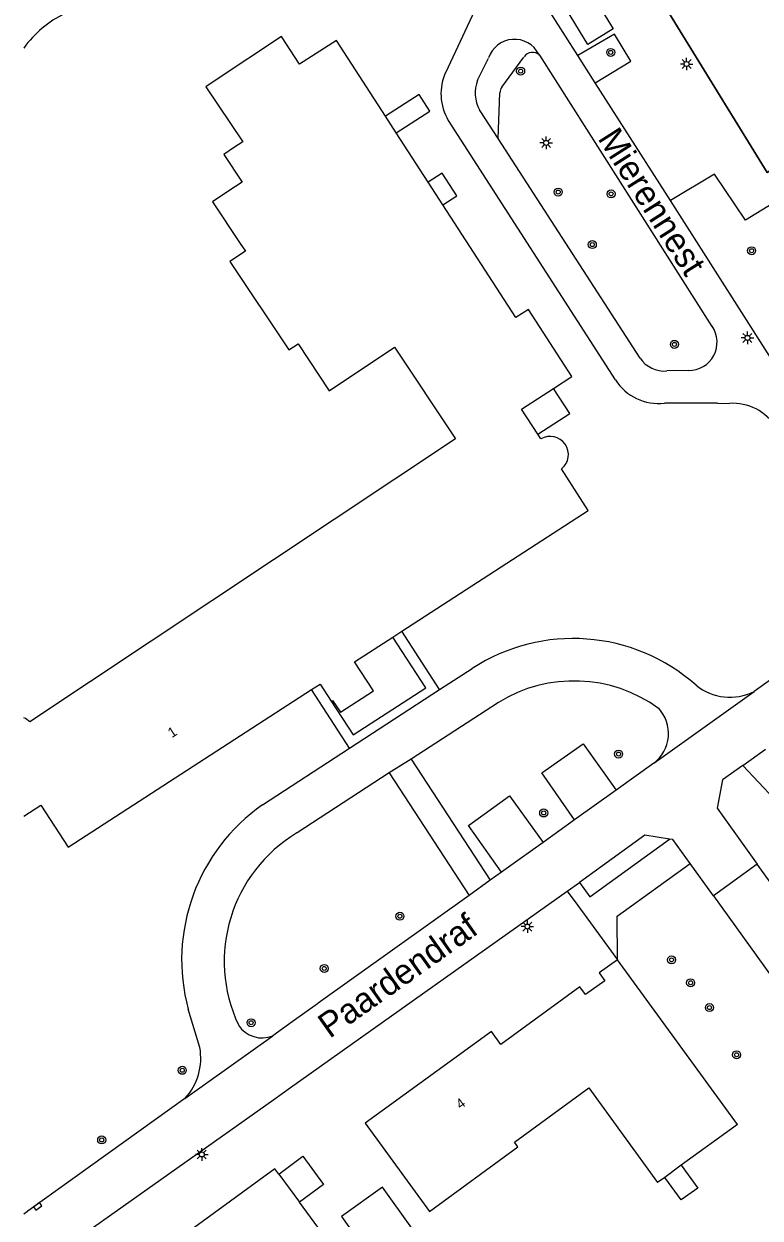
# Model space of a CAD drawing. Extents: x 141000 to 143000, y 400580 to 403500.
# Drawn here: x 141000 to 141073.5, y 403024.1 to 403143.4 of the extents above; entities that cross this region are included whole.
import ezdxf

# ---------------------------------------------------------------- set-up
doc = ezdxf.new("R2010")
doc.units = 0
for name, color, linetype in [('gg-afsc-erfafscheiding', 7, 'Continuous'), ('gg-afsc-hekwerk', 7, 'Continuous'), ('gg-anno-huisnummerreeks BGT', 7, 'Continuous'), ('gg-anno-openbare ruimte label', 7, 'Continuous'), ('gg-bbg-bijgebouw', 7, 'Continuous'), ('gg-bbg-gedigitaliseerde bijgebouw', 7, 'Continuous'), ('gg-bbg-hoofdgebouw', 7, 'Continuous'), ('gg-bbg-luifel en loopbrug', 7, 'Continuous'), ('gg-bbg-tussenscheiding', 7, 'Continuous'), ('gg-knt-verharding', 7, 'Continuous'), ('gg-knt-verharding nz', 7, 'Continuous'), ('gt-grn-groengrens', 7, 'Continuous'), ('gt-grn-vlakafsluiter', 7, 'Continuous'), ('gt-symb-boom', 7, 'Continuous'), ('gt-symb-kolk', 7, 'Continuous'), ('gt-symb-lichtmast', 7, 'Continuous')]:
    doc.layers.add(name, color=color, linetype=linetype)

# ---------------------------------------------------------------- blocks, each defined once
blk = doc.blocks.new('gt0-LMAST')
at = {"layer": 'gt-symb-lichtmast'}
for p, q in [((-0.18, 0.17), (-0.45, 0.44)), ((-0.01, 0.25), (-0.01, 0.62)), ((0.17, 0.17), (0.44, 0.44)), ((-0.26, 0), (-0.63, 0)), ((-0.18, -0.18), (-0.45, -0.45)), ((-0.01, -0.25), (-0.01, -0.63)), ((0.44, -0.45), (0.17, -0.18)), ((0.24, 0), (0.62, 0))]:
    blk.add_line(p, q, dxfattribs=at)
blk.add_circle((-0.01, 0), 0.25, dxfattribs=at)
blk = doc.blocks.new('gt0-BOOM')
at = {"layer": 'gt-symb-boom'}
for radius in [0.4, 0.2]:
    blk.add_circle((0, 0), radius, dxfattribs=at)
blk = doc.blocks.new('gt0-KOLK')
at = {"layer": 'gt-symb-kolk'}
blk.add_lwpolyline([(0, 0), (0.37, 0), (0.37, 0.4), (-0.38, 0.4), (-0.38, 0), (0, 0)], dxfattribs=at)

msp = doc.modelspace()

# ---------------------------------------------------------------- linework, layer by layer
at = {"layer": 'gg-afsc-erfafscheiding'}
msp.add_line((141057.08, 403137.55), (141055.34, 403140.28), dxfattribs=at)
at = {"layer": 'gg-afsc-hekwerk'}
msp.add_lwpolyline([(141060.06, 403151.69), (141094.93, 403173.23), (141109.35, 403150.25), (141074.26, 403128.6), (141060.06, 403151.69)], dxfattribs=at)
at = {"layer": 'gg-bbg-bijgebouw'}
msp.add_lwpolyline([(141034.65, 403020.12), (141038.76, 403023.06), (141035.82, 403027.17), (141031.71, 403024.23), (141034.65, 403020.12)], dxfattribs=at)
at = {"layer": 'gg-bbg-gedigitaliseerde bijgebouw'}
for points in [[(141056.72, 403146.43), (141058.87, 403142.95), (141056.33, 403141.39), (141054.19, 403144.87)], [(141037.2, 403132.54), (141040.55, 403134.71), (141039.47, 403136.39), (141036.11, 403134.22)]]:
    msp.add_lwpolyline(points, dxfattribs=at)
at = {"layer": 'gg-bbg-hoofdgebouw'}
for p, q in [((141040.38, 403127.61), (141037.2, 403132.54)), ((141041.85, 403125.35), (141040.38, 403127.61)), ((141051.65, 403101.96), (141051.35, 403102.43)), ((141036.85, 403082.16), (141037.74, 403082.74)), ((141071.27, 403033.43), (141059.28, 403049.89)), ((141071.27, 403033.43), (141065.67, 403029.36)), ((141025.45, 403028.48), (141027.52, 403025.66)), ((141065.67, 403029.36), (141064.01, 403028.15)), ((141064.01, 403028.15), (141063.3, 403027.64))]:
    msp.add_line(p, q, dxfattribs=at)
for points in [[(141036.11, 403134.22), (141031.21, 403141.78), (141027.53, 403139.4), (141025.73, 403142.18), (141019.12, 403137.78), (141018.19, 403137.16), (141021.86, 403131.65), (141020.94, 403131.04), (141019.97, 403130.39), (141021.8, 403127.63), (141020.48, 403126.75), (141018.83, 403125.65), (141021.59, 403121.49), (141022.13, 403120.74), (141020.57, 403119.68), (141026.45, 403110.85), (141027.39, 403111.47), (141030.5, 403106.78), (141037.03, 403111.12), (141043.12, 403101.97), (141000.6, 403073.67), (141000.15, 403074.03), (141000, 403074.07)], [(141052.9, 403107.01), (141054.74, 403108.2), (141050.41, 403114.89), (141049.14, 403114.09), (141041.85, 403125.35)], [(141051.35, 403102.43), (141049.71, 403104.94), (141052.9, 403107.01)], [(141037.74, 403082.74), (141056.36, 403094.8), (141053.71, 403098.98)], [(141030.7, 403075.74), (141030.84, 403075.83), (141031.61, 403074.64), (141034.91, 403076.78), (141033.03, 403079.69), (141036.85, 403082.16)], [(141028.72, 403076.9), (141029.59, 403077.46), (141030.7, 403075.74)], [(141000, 403064.24), (141001.7, 403065.34), (141004.43, 403061.17), (141028.72, 403076.9)], [(141059.28, 403049.89), (141057.47, 403048.58), (141058.03, 403047.81), (141056.1, 403046.42), (141055.54, 403047.19), (141047.64, 403041.43), (141046.7, 403042.73), (141034.08, 403033.56), (141040.5, 403024.75), (141049.35, 403031.19), (141049, 403031.68), (141056.43, 403037.09), (141063.3, 403027.64)], [(141025.45, 403028.48), (141025.08, 403028.99), (141011.43, 403019.05)], [(141022.4, 403014.93), (141022.57, 403015.05), (141030.83, 403021.16), (141027.52, 403025.66)]]:
    msp.add_lwpolyline(points, dxfattribs=at)
msp.add_arc((141052.58, 403100.4), 1.81, 308.4698, 120.8064, dxfattribs=at)
at = {"layer": 'gg-bbg-luifel en loopbrug'}
for points in [[(141041.85, 403125.35), (141043.24, 403126.24), (141041.77, 403128.51), (141040.38, 403127.61)], [(141051.35, 403102.43), (141054.53, 403104.5), (141052.9, 403107.01)], [(141030.7, 403075.74), (141032.88, 403072.38), (141040.14, 403077.09), (141036.85, 403082.16)], [(141025.45, 403028.48), (141027.87, 403030.26), (141029.94, 403027.44), (141027.52, 403025.66)], [(141065.67, 403029.36), (141067.33, 403027.07), (141065.65, 403025.89), (141064.01, 403028.15)]]:
    msp.add_lwpolyline(points, dxfattribs=at)
at = {"layer": 'gg-bbg-tussenscheiding'}
msp.add_line((141037.2, 403132.54), (141036.11, 403134.22), dxfattribs=at)
at = {"layer": 'gg-knt-verharding'}
for p, q in [((141055.34, 403140.28), (141050.74, 403147.51)), ((141045.23, 403145.26), (141042.14, 403138.63)), ((141051.51, 403140.3), (141051.44, 403140.41)), ((141045.32, 403137.8), (141046.41, 403140.03)), ((141051.51, 403140.3), (141068.73, 403113.21)), ((141064.58, 403125.78), (141057.08, 403137.55)), ((141059.09, 403107.86), (141042.4, 403133.79)), ((141061.56, 403110.03), (141047.36, 403131.97)), ((141077.33, 403105.75), (141064.58, 403125.78)), ((141066.38, 403108.8), (141064.22, 403108.75)), ((141069.28, 403105.52), (141063.99, 403105.53)), ((141069.28, 403105.52), (141070.47, 403105.51)), ((141082.19, 403083.34), (141072.93, 403076.71)), ((141041.53, 403076.9), (141037.74, 403082.74)), ((141041.53, 403076.9), (141044.77, 403079)), ((141032.52, 403071.04), (141028.72, 403076.9)), ((141047.4, 403075.62), (141038.68, 403069.96)), ((141023.84, 403065.38), (141032.52, 403071.04)), ((141038.68, 403069.96), (141046.56, 403057.84)), ((141071.83, 403069.33), (141074.09, 403070.94)), ((141062.93, 403069.56), (141059.15, 403066.85)), ((141071.83, 403069.33), (141074.93, 403065.98)), ((141036.49, 403068.58), (141027.28, 403062.58)), ((141036.49, 403068.58), (141044.47, 403056.34)), ((141059.15, 403066.85), (141055.01, 403063.89)), ((141055.01, 403063.89), (141051.86, 403061.63)), ((141068.88, 403056.29), (141066.55, 403059.51)), ((141073.24, 403059.44), (141068.88, 403056.29)), ((141077.74, 403053.2), (141073.24, 403059.44)), ((141047.71, 403058.66), (141046.56, 403057.84)), ((141046.56, 403057.84), (141044.47, 403056.34)), ((141054.27, 403056.76), (141055.49, 403057.63)), ((141054.27, 403056.76), (141055.32, 403055.32)), ((141068.88, 403056.29), (141096.13, 403018.32)), ((141017.57, 403041.14), (141016.41, 403044.96)), ((141000, 403024.52), (141000.36, 403024.78))]:
    msp.add_line(p, q, dxfattribs=at)
for points in [[(141054.55, 403150.07), (141057.4, 403145.7), (141059.93, 403147.32), (141056.4, 403152.91), (141094.62, 403176.46), (141102.17, 403164.21), (141102.7, 403164.56), (141105.03, 403160.96), (141104.42, 403160.54), (141111.86, 403148.25), (141072.07, 403123.82), (141069, 403128.42), (141064.58, 403125.78)], [(141109.35, 403150.25), (141094.93, 403173.23), (141060.06, 403151.69), (141074.26, 403128.6), (141109.35, 403150.25)], [(141057.08, 403137.55), (141060.64, 403139.71), (141058.98, 403142.42), (141055.34, 403140.28)], [(141047.36, 403131.97), (141045.56, 403134.75), (141045.5, 403134.84)], [(141055.01, 403063.89), (141051.74, 403068.57), (141055.87, 403071.47), (141059.15, 403066.85)], [(141071.83, 403069.33), (141069.79, 403067.87), (141069.26, 403065.05), (141073.24, 403059.44)], [(141047.71, 403058.66), (141044.4, 403063.33), (141048.5, 403066.27), (141051.86, 403061.63)], [(141051.86, 403061.63), (141050.59, 403060.72), (141049.58, 403060), (141047.71, 403058.66)], [(141064.48, 403061.96), (141062.01, 403062.34), (141055.49, 403057.63)], [(141055.49, 403057.63), (141056.53, 403056.2), (141064.48, 403061.96)], [(141066.55, 403059.51), (141064.81, 403061.91), (141064.48, 403061.96)], [(141059.28, 403049.89), (141059.25, 403054.25), (141066.55, 403059.51)], [(141000.61, 403018.66), (141001.04, 403018.97), (141024.96, 403035.95), (141026.63, 403037.14), (141054.27, 403056.76)], [(141044.47, 403056.34), (141029.38, 403045.55), (141029.33, 403045.51), (141026.81, 403043.7), (141024.87, 403042.31)], [(141016.09, 403036.04), (141000.51, 403024.88), (141000.36, 403024.78)]]:
    msp.add_lwpolyline(points, dxfattribs=at)
for centre, radius, start, end in [((141008.67, 403134.89), 10.62, 115.5854, 144.7235), ((141049, 403139.17), 2.73, 27.0386, 161.5341), ((141046.86, 403136.46), 5.2, 155.2991, 210.8545), ((141048.67, 403136.52), 3.59, 159.0325, 207.8526), ((141066.43, 403111.61), 2.81, 269.0996, 34.8243), ((141063.97, 403111.64), 2.9, 213.7414, 274.8996), ((141063.39, 403110.6), 5.1, 212.4457, 276.7383), ((141070.78, 403100.35), 5.17, 32.3901, 93.3858), ((141054.87, 403063.55), 18.46, 48.3559, 123.1711), ((141054.96, 403063.41), 14.36, 53.9893, 121.7899), ((141070.52, 403081.48), 5.34, 230.7467, 296.8574), ((141060.66, 403072.51), 3.73, 307.5813, 42.5189), ((141034.62, 403049.9), 18.86, 124.8483, 195.1815), ((141034.97, 403049.75), 14.96, 120.9432, 205.1913), ((141023.78, 403044.88), 2.79, 212.6282, 292.9319), ((141011.76, 403040.06), 5.91, 317.1176, 10.5294)]:
    msp.add_arc(centre, radius, start, end, dxfattribs=at)
at = {"layer": 'gg-knt-verharding nz'}
for p, q in [((141032.52, 403071.04), (141041.53, 403076.9)), ((141062.93, 403069.56), (141072.93, 403076.71)), ((141038.68, 403069.96), (141036.49, 403068.58)), ((141016.09, 403036.04), (141024.87, 403042.31))]:
    msp.add_line(p, q, dxfattribs=at)
at = {"layer": 'gt-grn-groengrens'}
for p, q in [((141047.74, 403137.11), (141049.95, 403140.13)), ((141047.36, 403131.97), (141047.54, 403136.56))]:
    msp.add_line(p, q, dxfattribs=at)
for centre, radius, start, end in [((141050.8, 403139.61), 0.992, 44.3115, 148.3204), ((141048.54, 403136.52), 0.998, 143.6947, 177.6974)]:
    msp.add_arc(centre, radius, start, end, dxfattribs=at)
at = {"layer": 'gt-grn-vlakafsluiter'}
msp.add_line((141055.32, 403055.32), (141059.28, 403049.89), dxfattribs=at)

# ---------------------------------------------------------------- block references
at = {"layer": 'gt-symb-boom'}
for p in [(141058.62, 403140.59), (141049.62, 403138.72), (141053.37, 403126.63), (141058.66, 403126.45), (141056.78, 403121.38), (141072.69, 403120.77), (141064.98, 403111.41), (141059.4, 403070.46), (141051.92, 403064.57), (141037.56, 403054.25), (141064.69, 403049.89), (141030, 403049.03), (141066.6, 403047.6), (141068.48, 403045.12), (141022.7, 403043.61), (141071.19, 403040.4), (141015.82, 403038.85), (141007.77, 403031.89)]:
    msp.add_blockref('gt0-BOOM', p, dxfattribs=at)
at = {"layer": 'gt-symb-kolk', "rotation": -144.41166614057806}
msp.add_blockref('gt0-KOLK', (141001.25, 403025.41), dxfattribs=at)
at = {"layer": 'gt-symb-lichtmast'}
for p in [(141066.21, 403139.43), (141052.17, 403131.55), (141072.28, 403112.06), (141050.3, 403053.22), (141017.77, 403030.44)]:
    msp.add_blockref('gt0-LMAST', p, dxfattribs=at)

# ---------------------------------------------------------------- texts
at = {"layer": 'gg-anno-huisnummerreeks BGT'}
for s, rotation, p in [('1', 32.9, (141014.78, 403072.04)), ('4', 36, (141043.61, 403034.92))]:
    msp.add_text(s, height=1, rotation=rotation, dxfattribs=at).set_placement(p)
at = {"layer": 'gg-anno-openbare ruimte label'}
for s, rotation, p in [('Mierennest', 302.5, (141057.26, 403132)), ('Paardendraf', 35.3, (141030.54, 403041.98))]:
    msp.add_text(s, height=2.5, rotation=rotation, dxfattribs=at).set_placement(p)

doc.saveas('drawing.dxf')
